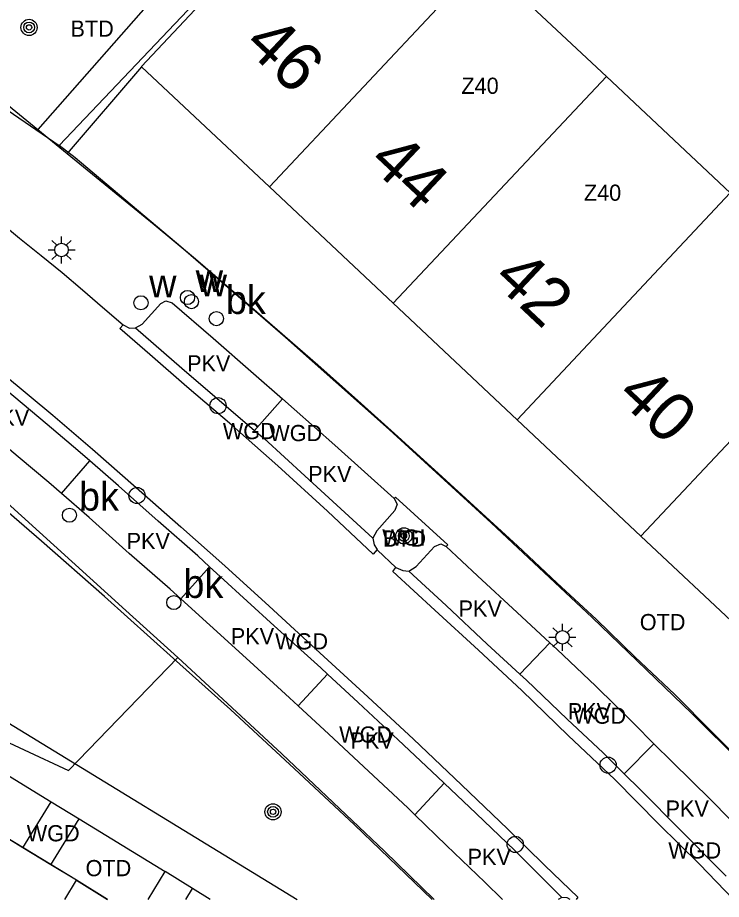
# Model space of a CAD drawing. Extents: x 198240 to 198429, y 356553 to 356721.
# Drawn here: x 198258.1 to 198284.19, y 356553.7 to 356586.38 of the extents above; entities that cross this region are included whole.
import ezdxf

# ---------------------------------------------------------------- set-up
doc = ezdxf.new("R2010")
doc.units = 0
for name, color, linetype in [('begroeid terreindeel kenmerkpunt', 7, 'Continuous'), ('BOOM', 7, 'Continuous'), ('Brandkraan_brandput', 7, 'Continuous'), ('grens individueel parkeervak', 7, 'Continuous'), ('Grens maaiveld', 7, 'Continuous'), ('hoofdgebouw', 7, 'Continuous'), ('huisnummerreeks BGT', 7, 'Continuous'), ('identificerend kenmerkpunt pand', 7, 'Continuous'), ('identificerend kenmerkpunt parkeervak', 7, 'Continuous'), ('kant verharding', 7, 'Continuous'), ('kolk', 7, 'Continuous'), ('LICHTMAST', 7, 'Continuous'), ('onbegroeid terreindeel kenmerkpunt', 7, 'Continuous'), ('perceelsgrens_definitief', 7, 'Continuous'), ('scheidingmuur boven maaiveld', 7, 'Continuous'), ('tussenmuur', 7, 'Continuous'), ('waterleidingput', 7, 'Continuous'), ('wegdeel kenmerkpunt', 7, 'Continuous'), ('weginrichtingselement', 7, 'Continuous')]:
    doc.layers.add(name, color=color, linetype=linetype)

msp = doc.modelspace()

# ---------------------------------------------------------------- linework, layer by layer
at = {"layer": 'BOOM'}
for centre, radius in [((198258.525, 356586.019), 0.3), ((198258.525, 356586.019), 0.2), ((198258.525, 356586.019), 0.1), ((198272.423, 356567.173), 0.3), ((198272.423, 356567.173), 0.2), ((198272.423, 356567.173), 0.1), ((198267.571, 356556.946), 0.3), ((198267.571, 356556.946), 0.2), ((198267.571, 356556.946), 0.1)]:
    msp.add_circle(centre, radius, dxfattribs=at)
at = {"layer": 'Brandkraan_brandput'}
for centre in [(198265.47, 356575.227), (198265.47, 356575.227), (198260.023, 356567.939), (198260.023, 356567.939), (198263.893, 356564.702), (198263.893, 356564.702)]:
    msp.add_circle(centre, 0.263, dxfattribs=at)
at = {"layer": 'grens individueel parkeervak'}
for p, q in [((198266.882, 356571.083), (198267.926, 356572.252)), ((198259.73, 356568.743), (198260.773, 356569.956)), ((198264.147, 356564.846), (198265.218, 356566.031)), ((198277.839, 356563.209), (198276.721, 356562.048)), ((198268.499, 356560.876), (198269.594, 356562.052)), ((198280.588, 356558.36), (198281.695, 356559.467)), ((198272.827, 356556.838), (198273.92, 356558.014))]:
    msp.add_line(p, q, dxfattribs=at)
at = {"layer": 'Grens maaiveld'}
for p, q in [((198262.699, 356584.562), (198259.936, 356581.349)), ((198256.006, 356559.368), (198259.345, 356557.319)), ((198258.3, 356555.616), (198259.345, 356557.319)), ((198259.345, 356557.319), (198260.377, 356556.686)), ((198258.3, 356555.616), (198255.928, 356557.066)), ((198259.333, 356554.985), (198260.377, 356556.686)), ((198260.377, 356556.686), (198263.566, 356554.73)), ((198259.333, 356554.985), (198258.3, 356555.616)), ((198260.28, 356554.407), (198259.333, 356554.985)), ((198262.935, 356553.702), (198263.566, 356554.73)), ((198264.586, 356554.104), (198263.566, 356554.73)), ((198260.28, 356554.407), (198261.435, 356553.702)), ((198264.339, 356553.702), (198264.586, 356554.104)), ((198265.242, 356553.702), (198264.586, 356554.104))]:
    msp.add_line(p, q, dxfattribs=at)
for points in [[(198272.277, 356597.868), (198267.761, 356592.361), (198258.856, 356582.232)], [(198271.436, 356566.664), (198271.285, 356566.496), (198269.591, 356568.086), (198267.747, 356569.766), (198266.045, 356571.273), (198264.38, 356572.702), (198262.998, 356573.901), (198261.888, 356574.859), (198262.011, 356574.998)], [(198255.592, 356574.585), (198255.699, 356574.762), (198257.573, 356573.165), (198259.411, 356571.648), (198260.875, 356570.386), (198262.5, 356568.968), (198264.152, 356567.503), (198265.781, 356566.067), (198267.427, 356564.565), (198269.308, 356562.845), (198271.085, 356561.21), (198272.778, 356559.643), (198274.563, 356557.947), (198276.281, 356556.309), (198277.654, 356554.959), (198278.872, 356553.781), (198278.805, 356553.702)], [(198284.644, 356553.702), (198283.387, 356555), (198281.872, 356556.493), (198280.238, 356558.141), (198278.516, 356559.778), (198276.797, 356561.449), (198275.184, 356562.933), (198273.567, 356564.419), (198272.007, 356565.849), (198272.129, 356565.996)]]:
    msp.add_lwpolyline(points, dxfattribs=at)
at = {"layer": 'hoofdgebouw'}
for p, q in [((198279.929, 356584.199), (198275.335, 356588.51)), ((198262.699, 356584.562), (198267.436, 356580.11)), ((198284.522, 356579.888), (198279.929, 356584.199)), ((198267.436, 356580.11), (198272.026, 356575.795)), ((198272.026, 356575.795), (198276.617, 356571.48)), ((198276.617, 356571.48), (198281.207, 356567.165)), ((198281.207, 356567.165), (198285.798, 356562.85))]:
    msp.add_line(p, q, dxfattribs=at)
msp.add_lwpolyline([(198270.587, 356592.966), (198262.695, 356584.566), (198262.699, 356584.562)], dxfattribs=at)
at = {"layer": 'kant verharding'}
for p, q in [((198256.204, 356584.398), (198258.856, 356582.232)), ((198258.856, 356582.232), (198259.936, 356581.349)), ((198246.362, 356567.205), (198268.466, 356553.702))]:
    msp.add_line(p, q, dxfattribs=at)
for points in [[(198259.936, 356581.349), (198263.162, 356578.714), (198264.691, 356577.443), (198266.216, 356576.128), (198267.724, 356574.825), (198269.227, 356573.509), (198270.721, 356572.194), (198272.197, 356570.855), (198273.693, 356569.495), (198275.162, 356568.148), (198276.635, 356566.799), (198278.09, 356565.437), (198279.565, 356564.071), (198280.999, 356562.677), (198282.453, 356561.301), (198283.864, 356559.891), (198285.266, 356558.474), (198286.669, 356557.036), (198288.064, 356555.615), (198289.442, 356554.173), (198289.902, 356553.702)], [(198255.653, 356580.25), (198255.998, 356579.968), (198256.636, 356579.462), (198257.404, 356578.839), (198258.176, 356578.204), (198258.972, 356577.566), (198259.754, 356576.936), (198260.504, 356576.293), (198261.252, 356575.651), (198262.011, 356574.998)], [(198262.472, 356574.882), (198262.721, 356575.025), (198263.406, 356575.781), (198263.602, 356575.88), (198263.831, 356575.812), (198265.351, 356574.501), (198266.848, 356573.196), (198267.926, 356572.252)], [(198262.011, 356574.998), (198262.015, 356574.995), (198262.255, 356574.876), (198262.472, 356574.882)], [(198262.472, 356574.882), (198264.186, 356573.388), (198266.882, 356571.083)], [(198260.773, 356569.956), (198260.331, 356570.341), (198259.198, 356571.307), (198257.655, 356572.598), (198255.749, 356574.163)], [(198273.472, 356553.702), (198272.817, 356554.33), (198270.586, 356556.469), (198268.355, 356558.558), (198265.988, 356560.735), (198263.879, 356562.635), (198261.324, 356564.926), (198258.988, 356566.982), (198256.674, 356568.965), (198254.222, 356571.03), (198251.842, 356572.999), (198249.557, 356572.425)], [(198259.73, 356568.743), (198259.258, 356569.155), (198258.124, 356570.109), (198256.585, 356571.386), (198255.033, 356572.668)], [(198267.926, 356572.252), (198268.357, 356571.874), (198269.857, 356570.538), (198272.064, 356568.559)], [(198266.882, 356571.083), (198267.236, 356570.78), (198268.749, 356569.401), (198271.275, 356567.086)], [(198265.218, 356566.031), (198264.787, 356566.433), (198263.315, 356567.72), (198261.835, 356569.031), (198260.773, 356569.956)], [(198264.147, 356564.846), (198263.754, 356565.2), (198262.242, 356566.525), (198260.753, 356567.849), (198259.73, 356568.743)], [(198272.064, 356568.559), (198272.173, 356568.343), (198272.09, 356568.113), (198271.421, 356567.365), (198271.275, 356567.086)], [(198272.064, 356568.559), (198272.11, 356568.61), (198274.05, 356566.847), (198273.988, 356566.779)], [(198271.275, 356567.086), (198271.317, 356566.841), (198271.436, 356566.664)], [(198272.601, 356565.868), (198272.872, 356566.035), (198273.556, 356566.774), (198273.788, 356566.874), (198273.988, 356566.779)], [(198273.988, 356566.779), (198275.147, 356565.698), (198276.623, 356564.337), (198277.839, 356563.209)], [(198271.436, 356566.664), (198271.447, 356566.647), (198272.127, 356565.997), (198272.129, 356565.996)], [(198269.594, 356562.052), (198269.346, 356562.282), (198267.614, 356563.842), (198265.605, 356565.67), (198265.218, 356566.031)], [(198272.129, 356565.996), (198272.379, 356565.892), (198272.601, 356565.868)], [(198272.601, 356565.868), (198273.99, 356564.596), (198275.509, 356563.162), (198276.721, 356562.048)], [(198268.499, 356560.876), (198268.18, 356561.168), (198266.706, 356562.515), (198265.233, 356563.868), (198264.147, 356564.846)], [(198277.839, 356563.209), (198278.096, 356562.97), (198279.539, 356561.602), (198280.96, 356560.202), (198281.695, 356559.467)], [(198273.92, 356558.014), (198273.675, 356558.247), (198272.215, 356559.62), (198270.729, 356561.001), (198269.594, 356562.052)], [(198276.721, 356562.048), (198276.963, 356561.826), (198278.471, 356560.385), (198279.81, 356559.131), (198280.588, 356558.36)], [(198272.827, 356556.838), (198272.568, 356557.088), (198271.112, 356558.449), (198269.643, 356559.828), (198268.499, 356560.876)], [(198281.695, 356559.467), (198282.364, 356558.797), (198283.801, 356557.392), (198285.2, 356555.966), (198285.496, 356555.657)], [(198280.588, 356558.36), (198281.178, 356557.775), (198282.686, 356556.26), (198284.072, 356554.859), (198284.368, 356554.558)], [(198278.28, 356553.772), (198276.537, 356555.509), (198275.102, 356556.888), (198273.92, 356558.014)], [(198276.075, 356553.702), (198275.429, 356554.341), (198274.005, 356555.7), (198272.827, 356556.838)], [(198278.28, 356553.772), (198278.149, 356553.702)], [(198278.585, 356553.702), (198278.475, 356553.758), (198278.28, 356553.772)]]:
    msp.add_lwpolyline(points, dxfattribs=at)
at = {"layer": 'kolk'}
for centre in [(198265.532, 356571.998), (198262.529, 356568.669), (198279.995, 356558.677), (198276.551, 356555.737)]:
    msp.add_circle(centre, 0.3, dxfattribs=at)
at = {"layer": 'LICHTMAST'}
for p, q in [((198259.729, 356578.022), (198259.729, 356578.272)), ((198259.552, 356577.949), (198259.375, 356578.126)), ((198259.906, 356577.949), (198260.083, 356578.126)), ((198259.229, 356577.772), (198259.479, 356577.772)), ((198259.375, 356577.418), (198259.552, 356577.595)), ((198259.729, 356577.272), (198259.729, 356577.522)), ((198260.083, 356577.418), (198259.906, 356577.595)), ((198259.979, 356577.772), (198260.229, 356577.772)), ((198278.125, 356563.591), (198277.948, 356563.768)), ((198278.302, 356563.664), (198278.302, 356563.914)), ((198278.479, 356563.591), (198278.656, 356563.768)), ((198277.802, 356563.414), (198278.052, 356563.414)), ((198277.948, 356563.06), (198278.125, 356563.237)), ((198278.302, 356562.914), (198278.302, 356563.164)), ((198278.656, 356563.06), (198278.479, 356563.237)), ((198278.552, 356563.414), (198278.802, 356563.414))]:
    msp.add_line(p, q, dxfattribs=at)
for centre in [(198259.729, 356577.772), (198278.302, 356563.414)]:
    msp.add_circle(centre, 0.25, dxfattribs=at)
at = {"layer": 'perceelsgrens_definitief'}
for points in [[(198259.64, 356581.648), (198275.847, 356598.687)], [(198243.211, 356592.912), (198259.64, 356581.648)], [(198260.232, 356581.19), (198259.64, 356581.648)], [(198289.969, 356553.702), (198286.746, 356556.976), (198283.098, 356560.585), (198279.403, 356564.145), (198275.66, 356567.655), (198271.871, 356571.116), (198268.036, 356574.525), (198264.156, 356577.884), (198260.232, 356581.19)], [(198262.119, 356564.407), (198256.224, 356569.728)], [(198264.044, 356562.661), (198262.119, 356564.407)], [(198250.107, 356563.075), (198259.986, 356558.483), (198264.044, 356562.661)], [(198273.544, 356553.702), (198271.702, 356555.491), (198267.894, 356559.099), (198264.044, 356562.661)]]:
    msp.add_lwpolyline(points, dxfattribs=at)
at = {"layer": 'scheidingmuur boven maaiveld'}
for p, q in [((198260.28, 356554.407), (198255.928, 356557.066)), ((198261.435, 356553.702), (198260.28, 356554.407))]:
    msp.add_line(p, q, dxfattribs=at)
at = {"layer": 'tussenmuur'}
for p, q in [((198267.436, 356580.11), (198275.335, 356588.51)), ((198272.026, 356575.795), (198279.929, 356584.199)), ((198276.617, 356571.48), (198284.522, 356579.888)), ((198281.207, 356567.165), (198289.116, 356575.577)), ((198259.848, 356553.702), (198260.28, 356554.407))]:
    msp.add_line(p, q, dxfattribs=at)
at = {"layer": 'waterleidingput'}
for centre in [(198264.399, 356576.009), (198264.399, 356576.009), (198262.672, 356575.813), (198262.672, 356575.813), (198264.546, 356575.856), (198264.546, 356575.856)]:
    msp.add_circle(centre, 0.263, dxfattribs=at)

# ---------------------------------------------------------------- texts
at = {"layer": 'begroeid terreindeel kenmerkpunt'}
for p in [(198260.061, 356585.675), (198271.639, 356566.774)]:
    msp.add_text('BTD', height=0.6, dxfattribs=at).set_placement(p)
at = {"layer": 'Brandkraan_brandput'}
for p in [(198265.822, 356575.399), (198260.375, 356568.111), (198264.245, 356564.874)]:
    msp.add_text('bk', height=1.05, dxfattribs=at).set_placement(p)
at = {"layer": 'huisnummerreeks BGT'}
for s, p in [('46', (198266.43, 356585.308)), ('44', (198271.051, 356580.966)), ('42', (198275.663, 356576.63)), ('40', (198280.258, 356572.312))]:
    msp.add_text(s, height=1.8, rotation=316.8, dxfattribs=at).set_placement(p)
at = {"layer": 'identificerend kenmerkpunt pand'}
for p in [(198274.555, 356583.557), (198279.097, 356579.594)]:
    msp.add_text('Z40', height=0.6, dxfattribs=at).set_placement(p)
at = {"layer": 'identificerend kenmerkpunt parkeervak'}
for p in [(198264.384, 356573.268), (198256.925, 356571.257), (198268.875, 356569.168), (198262.142, 356566.685), (198274.451, 356564.18), (198266.005, 356563.156), (198278.498, 356560.376), (198270.441, 356559.29), (198282.126, 356556.767), (198274.785, 356554.976)]:
    msp.add_text('PKV', height=0.6, dxfattribs=at).set_placement(p)
at = {"layer": 'onbegroeid terreindeel kenmerkpunt'}
for p in [(198281.169, 356563.678), (198260.621, 356554.56)]:
    msp.add_text('OTD', height=0.6, dxfattribs=at).set_placement(p)
at = {"layer": 'waterleidingput'}
for p in [(198264.703, 356576.207), (198264.85, 356576.054), (198262.976, 356576.011)]:
    msp.add_text('w', height=1.05, dxfattribs=at).set_placement(p)
at = {"layer": 'wegdeel kenmerkpunt'}
for p in [(198265.71, 356570.758), (198267.432, 356570.685), (198267.649, 356562.965), (198278.7, 356560.21), (198270.024, 356559.51), (198258.439, 356555.852), (198282.228, 356555.214)]:
    msp.add_text('WGD', height=0.6, dxfattribs=at).set_placement(p)
at = {"layer": 'weginrichtingselement'}
msp.add_text('WGI', height=0.6, dxfattribs=at).set_placement((198271.62, 356566.814))

doc.saveas('drawing.dxf')
